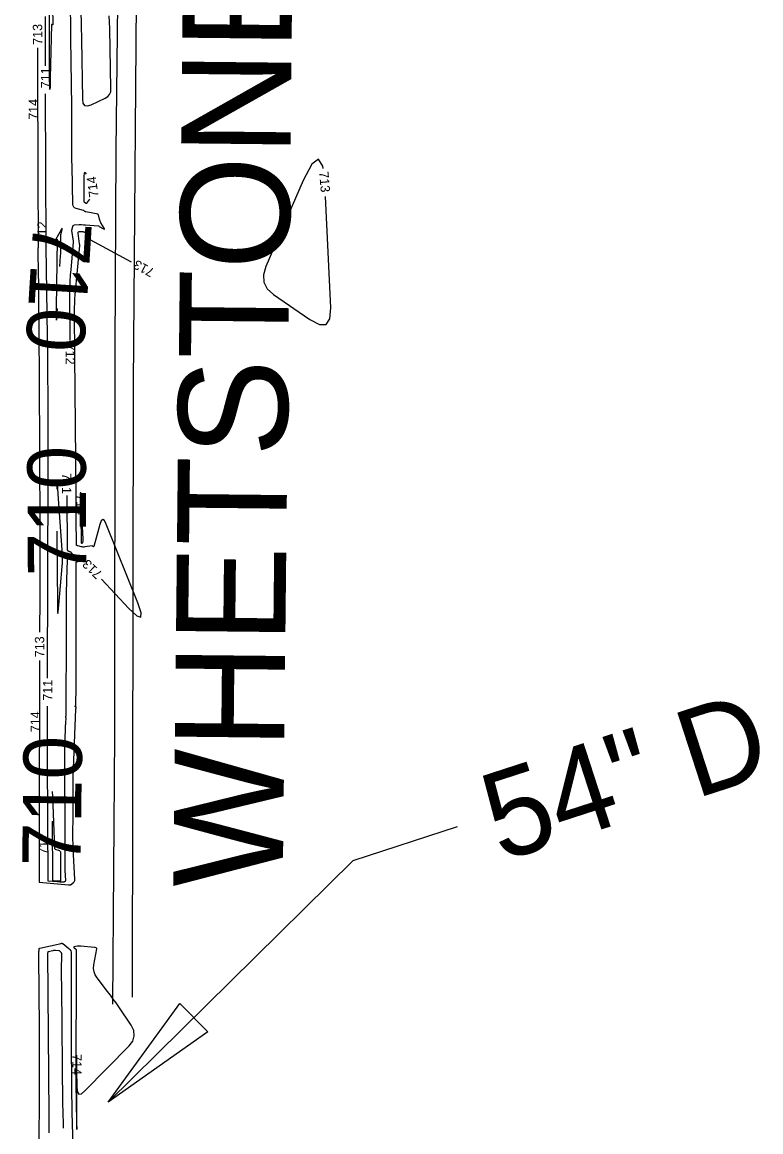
# Model space of a CAD drawing. Extents: x -468548933 to 3387700, y -306089263 to 1207014.
# Drawn here: x 1835224.3 to 1835540.3, y 536770.1 to 537244.7 of the extents above; entities that cross this region are included whole.
import ezdxf

# ---------------------------------------------------------------- set-up
doc = ezdxf.new("R2010")
doc.units = 0
for name, color, linetype in [('DT_X_Contour_Minor', 7, 'Continuous'), ('Level 19', 7, 'Continuous'), ('Level 40', 7, 'Continuous'), ('Level 56', 7, 'Continuous')]:
    doc.layers.add(name, color=color, linetype=linetype)

msp = doc.modelspace()

# ---------------------------------------------------------------- linework, layer by layer
at = {"layer": 'DT_X_Contour_Minor'}
for points in [[(1835245.53, 537208.54), (1835245.2, 537237.69), (1835245.13, 537243.93), (1835245.05, 537250.18), (1835244.96, 537256.42), (1835244.87, 537262.67), (1835244.29, 537300.93), (1835244.27, 537303.35), (1835244.26, 537305.76), (1835244.26, 537308.18), (1835244.29, 537310.6), (1835244.4, 537318.49), (1835244.43, 537320.18), (1835244.45, 537321.87), (1835244.47, 537323.56), (1835244.5, 537325.26), (1835244.63, 537334.22)], [(1835237.1, 537258.77), (1835237.41, 537243.69), (1835237.4, 537243.62), (1835237.38, 537243.59), (1835237.33, 537243.58), (1835237.27, 537243.61), (1835237.05, 537243.75), (1835237, 537243.76), (1835236.97, 537243.76), (1835236.95, 537243.74), (1835236.94, 537243.69), (1835236.35, 537220.78), (1835236.24, 537217.1), (1835236.16, 537215.87), (1835236.1, 537217.1), (1835236.07, 537220.78), (1835235.98, 537252.2)], [(1835249.44, 537249.82), (1835249.54, 537243.5), (1835249.64, 537237.19), (1835250.09, 537211.76), (1835250.35, 537210.1), (1835251.06, 537209.15), (1835252.22, 537208.93), (1835253.83, 537209.43), (1835259.82, 537212.23), (1835260.94, 537212.93), (1835261.73, 537213.84), (1835262.2, 537214.95), (1835262.33, 537216.26), (1835261.78, 537241.97), (1835261.6, 537247.47)], [(1835234.35, 537226.13), (1835234.34, 537229.07), (1835234.33, 537233.31), (1835234.29, 537247.16)], [(1835230.91, 537233.73), (1835230.92, 537229.63), (1835231.08, 537175.02), (1835231.09, 537171.97), (1835231.09, 537168.92), (1835231.1, 537165.87), (1835231.11, 537162.82), (1835231.15, 537148.61), (1835231.15, 537148.6), (1835231.15, 537148.59), (1835231.16, 537148.58), (1835231.16, 537148.57), (1835231.17, 537148.53), (1835231.18, 537148.53), (1835231.18, 537148.52), (1835231.18, 537148.51), (1835231.18, 537148.51), (1835231.11, 537148.17), (1835231.09, 537148.09), (1835231.08, 537148.02), (1835231.08, 537147.94), (1835231.08, 537147.87), (1835231.22, 537136.27), (1835231.25, 537133.79), (1835231.28, 537131.3), (1835231.3, 537128.82), (1835231.32, 537126.33), (1835231.58, 537093.92), (1835231.63, 537086.98), (1835231.67, 537080.03), (1835231.7, 537073.09), (1835231.72, 537066.14), (1835231.82, 537022.38), (1835231.83, 537016.41), (1835231.83, 537010.45), (1835231.83, 537004.49), (1835231.82, 536998.52), (1835231.78, 536983.74)], [(1835235.23, 536964.15), (1835235.46, 537051.06), (1835235.46, 537054.46), (1835235.47, 537057.86), (1835235.46, 537061.26), (1835235.46, 537064.66), (1835235.43, 537075.76), (1835235.43, 537078.14), (1835235.42, 537080.52), (1835235.4, 537082.9), (1835235.39, 537085.29), (1835235.32, 537093.64), (1835235.3, 537095.44), (1835235.29, 537097.23), (1835235.27, 537099.02), (1835235.25, 537100.81), (1835234.65, 537148.62), (1835234.65, 537148.64), (1835234.65, 537148.65), (1835234.65, 537148.66), (1835234.66, 537148.68), (1835234.67, 537148.73), (1835234.67, 537148.74), (1835234.67, 537148.75), (1835234.67, 537148.75), (1835234.66, 537148.76), (1835234.6, 537148.92), (1835234.58, 537148.96), (1835234.57, 537148.99), (1835234.57, 537149.03), (1835234.57, 537149.07), (1835234.38, 537214.13)], [(1835244.87, 537108.57), (1835244.79, 537128.99), (1835244.81, 537131.49), (1835244.89, 537133.99), (1835245.04, 537136.49), (1835245.24, 537138.98), (1835246.32, 537150.51), (1835246.33, 537150.56), (1835246.32, 537150.61), (1835246.32, 537150.67), (1835246.31, 537150.72), (1835246.26, 537150.89), (1835246.25, 537150.93), (1835246.24, 537150.96), (1835246.24, 537151), (1835246.23, 537151.04), (1835245.63, 537155.61), (1835245.62, 537155.63), (1835245.62, 537155.65), (1835245.62, 537155.67), (1835245.61, 537155.69), (1835245.6, 537155.76), (1835245.6, 537155.77), (1835245.6, 537155.79), (1835245.6, 537155.8), (1835245.61, 537155.81), (1835245.96, 537157.31), (1835246.07, 537157.59), (1835246.24, 537157.8), (1835246.48, 537157.93), (1835246.77, 537157.99), (1835248.66, 537158.12), (1835248.93, 537158.13), (1835249.2, 537158.14), (1835249.47, 537158.14), (1835249.73, 537158.14), (1835250.61, 537158.11), (1835250.8, 537158.1), (1835250.98, 537158.09), (1835251.17, 537158.08), (1835251.36, 537158.06), (1835256.97, 537157.61), (1835257.02, 537157.6), (1835257.07, 537157.58), (1835257.11, 537157.56), (1835257.15, 537157.52), (1835257.31, 537157.34), (1835257.31, 537157.33), (1835257.32, 537157.33), (1835257.32, 537157.32), (1835257.32, 537157.32), (1835257.31, 537157.3), (1835257.31, 537157.29), (1835257.31, 537157.29), (1835257.31, 537157.29), (1835257.32, 537157.29), (1835259.12, 537156.32), (1835259.43, 537156.19), (1835259.58, 537156.2), (1835259.58, 537156.35), (1835259.43, 537156.65), (1835258.04, 537158.89), (1835257.83, 537159.26), (1835257.66, 537159.64), (1835257.51, 537160.03), (1835257.39, 537160.43), (1835256.94, 537162.3), (1835256.93, 537162.33), (1835256.92, 537162.35), (1835256.91, 537162.38), (1835256.9, 537162.41), (1835256.87, 537162.51), (1835256.87, 537162.52), (1835256.86, 537162.54), (1835256.84, 537162.55), (1835256.82, 537162.55), (1835251.52, 537163.61), (1835251.41, 537163.64), (1835251.3, 537163.68), (1835251.2, 537163.73), (1835251.11, 537163.79), (1835250.81, 537164.03), (1835250.74, 537164.07), (1835250.67, 537164.11), (1835250.6, 537164.14), (1835250.52, 537164.17), (1835247.38, 537165.04), (1835246.78, 537165.29), (1835246.36, 537165.67), (1835246.1, 537166.18), (1835246, 537166.81), (1835245.67, 537183.09), (1835245.63, 537185.61), (1835245.6, 537188.14), (1835245.58, 537190.67), (1835245.57, 537193.2), (1835245.57, 537201.46), (1835245.57, 537203.23), (1835245.56, 537205), (1835245.55, 537206.77), (1835245.53, 537208.54)], [(1835353.04, 537182.16), (1835352.92, 537183.17), (1835351.07, 537186.07), (1835348.3, 537184.02), (1835344.61, 537177.03), (1835328.51, 537140.24), (1835327.51, 537136.72), (1835327.74, 537133.55), (1835329.21, 537130.73), (1835331.91, 537128.25)], [(1835250.76, 537179.05), (1835250.64, 537168.41), (1835250.66, 537168.24), (1835250.71, 537168.09), (1835250.8, 537167.95), (1835250.92, 537167.83), (1835251.49, 537167.4), (1835251.53, 537167.36), (1835251.58, 537167.34), (1835251.63, 537167.32), (1835251.69, 537167.3), (1835251.87, 537167.27), (1835251.9, 537167.27), (1835251.94, 537167.27), (1835251.97, 537167.29), (1835251.99, 537167.32), (1835253.24, 537168.96)], [(1835251.8, 537179.66), (1835251.46, 537180.24), (1835251.08, 537180.49), (1835250.85, 537180.1), (1835250.76, 537179.05)], [(1835331.91, 537128.25), (1835347.38, 537117.52), (1835351.49, 537115.36), (1835354.35, 537115.47), (1835355.96, 537117.84), (1835356.32, 537122.47), (1835354.1, 537170.22)], [(1835240.49, 537140.21), (1835240.77, 537144.78), (1835240.82, 537145.71), (1835240.86, 537146.64), (1835240.88, 537147.58), (1835240.88, 537148.51), (1835240.86, 537152.77), (1835240.86, 537152.82), (1835240.87, 537152.88), (1835240.87, 537152.93), (1835240.87, 537152.98), (1835240.9, 537153.23), (1835240.9, 537153.23), (1835240.9, 537153.23), (1835240.9, 537153.24), (1835240.9, 537153.24), (1835240.9, 537153.24), (1835240.9, 537153.24), (1835240.9, 537153.24), (1835240.9, 537153.24), (1835240.89, 537153.24), (1835240.89, 537153.31), (1835240.88, 537153.33), (1835240.88, 537153.34), (1835240.88, 537153.36), (1835240.88, 537153.37), (1835240.83, 537153.66), (1835240.83, 537153.72), (1835240.82, 537153.78), (1835240.83, 537153.84), (1835240.84, 537153.91), (1835241.37, 537156.1), (1835241.43, 537156.45), (1835241.41, 537156.59), (1835241.31, 537156.51), (1835241.11, 537156.2), (1835238.52, 537151.7), (1835238.48, 537151.61), (1835238.48, 537151.57), (1835238.52, 537151.57), (1835238.61, 537151.61)], [(1835258.24, 537006.5), (1835270, 536993.95), (1835273.33, 536990.8), (1835275.06, 536990.15), (1835275.21, 536992), (1835273.77, 536996.35), (1835260.33, 537030.03), (1835259.56, 537031.52), (1835258.84, 537031.99), (1835258.18, 537031.45), (1835257.57, 537029.89), (1835254.93, 537020.44), (1835254.89, 537020.36), (1835254.84, 537020.32), (1835254.79, 537020.33), (1835254.72, 537020.39), (1835254.47, 537020.64), (1835254.42, 537020.69), (1835254.35, 537020.72), (1835254.29, 537020.73), (1835254.22, 537020.73), (1835251.1, 537020.25), (1835250.73, 537020.21), (1835250.37, 537020.21), (1835250, 537020.25), (1835249.64, 537020.32), (1835248.08, 537020.71), (1835248.02, 537020.73), (1835247.96, 537020.75), (1835247.9, 537020.78), (1835247.84, 537020.81), (1835247.65, 537020.91), (1835247.62, 537020.94), (1835247.59, 537020.97), (1835247.58, 537021.01), (1835247.57, 537021.05), (1835247.49, 537032.53), (1835247.47, 537034.99), (1835247.45, 537037.45), (1835247.43, 537039.91), (1835247.41, 537042.37), (1835246.84, 537102.21), (1835246.82, 537104.79), (1835246.8, 537107.37), (1835246.79, 537109.95), (1835246.77, 537112.52), (1835246.74, 537120.95), (1835246.75, 537122.75), (1835246.81, 537124.56), (1835246.92, 537126.36), (1835247.06, 537128.16), (1835249.04, 537149.14), (1835249.04, 537149.22), (1835249.04, 537149.3), (1835249.03, 537149.38), (1835249.01, 537149.46), (1835248.94, 537149.71), (1835248.93, 537149.77), (1835248.92, 537149.82), (1835248.91, 537149.88), (1835248.9, 537149.94), (1835248.29, 537154.51), (1835248.3, 537154.86), (1835248.41, 537155.1), (1835248.65, 537155.23), (1835248.99, 537155.26), (1835250.31, 537155.16), (1835250.58, 537155.12), (1835250.83, 537155.03), (1835251.05, 537154.88), (1835251.25, 537154.69), (1835253.18, 537152.46), (1835253.22, 537152.4), (1835253.25, 537152.33), (1835253.26, 537152.25), (1835253.25, 537152.17), (1835253.19, 537151.9), (1835253.19, 537151.84), (1835253.2, 537151.8), (1835253.23, 537151.76), (1835253.27, 537151.73), (1835270.89, 537142.29)], [(1835238.61, 537151.61), (1835239.08, 537151.88), (1835239.2, 537151.94), (1835239.29, 537151.92), (1835239.35, 537151.85), (1835239.36, 537151.72), (1835238.92, 537122.47), (1835238.89, 537118.58), (1835238.96, 537117.27), (1835239.13, 537118.57), (1835239.38, 537122.24)], [(1835240.03, 536995.31), (1835241.45, 537011.91), (1835241.49, 537012.43), (1835241.52, 537012.94), (1835241.55, 537013.46), (1835241.56, 537013.98), (1835241.63, 537016.36), (1835241.63, 537016.38), (1835241.64, 537016.39), (1835241.65, 537016.41), (1835241.67, 537016.41), (1835241.73, 537016.44), (1835241.74, 537016.45), (1835241.74, 537016.45), (1835241.74, 537016.46), (1835241.73, 537016.47), (1835241.7, 537016.51), (1835241.69, 537016.52), (1835241.69, 537016.53), (1835241.68, 537016.54), (1835241.68, 537016.55), (1835241.63, 537016.75), (1835241.62, 537016.79), (1835241.61, 537016.84), (1835241.6, 537016.88), (1835241.6, 537016.93), (1835239.79, 537042.91), (1835239.46, 537047.09), (1835239.23, 537048.47), (1835239.11, 537047.07), (1835239.1, 537045.03)], [(1835243.37, 537042.2), (1835243.53, 537019.29), (1835243.55, 537019.12), (1835243.61, 537018.96), (1835243.72, 537018.84), (1835243.86, 537018.73), (1835244.5, 537018.37), (1835244.56, 537018.34), (1835244.63, 537018.31), (1835244.69, 537018.28), (1835244.76, 537018.26), (1835244.99, 537018.21), (1835245.03, 537018.19), (1835245.07, 537018.17), (1835245.09, 537018.13), (1835245.11, 537018.09), (1835245.17, 537017.91), (1835245.19, 537017.88), (1835245.2, 537017.84), (1835245.22, 537017.81), (1835245.25, 537017.77), (1835245.9, 537017), (1835246, 537016.85), (1835246.01, 537016.71), (1835245.94, 537016.59), (1835245.78, 537016.5), (1835244.23, 537015.82), (1835243.93, 537015.64), (1835243.72, 537015.41), (1835243.59, 537015.13), (1835243.54, 537014.8), (1835243.29, 537005.98), (1835243.24, 537004.09), (1835243.21, 537002.2), (1835243.19, 537000.31), (1835243.19, 536998.42), (1835243.19, 536991.11), (1835243.19, 536989.54), (1835243.19, 536987.97), (1835243.18, 536986.41), (1835243.18, 536984.84), (1835243.01, 536948.28), (1835243.01, 536948.23), (1835243, 536948.18), (1835242.99, 536948.13), (1835242.98, 536948.08), (1835242.94, 536947.92), (1835242.93, 536947.89), (1835242.93, 536947.86), (1835242.92, 536947.82), (1835242.92, 536947.79), (1835242.91, 536947.21), (1835242.91, 536947.2), (1835242.91, 536947.19), (1835242.92, 536947.18), (1835242.94, 536947.18), (1835242.99, 536947.18), (1835243, 536947.18), (1835243.01, 536947.17), (1835243.01, 536947.17), (1835243.01, 536947.16), (1835242.84, 536944.83), (1835242.81, 536944.33), (1835242.78, 536943.83), (1835242.76, 536943.33), (1835242.73, 536942.84), (1835242.54, 536937.89), (1835242.51, 536936.83), (1835242.48, 536935.78), (1835242.47, 536934.72), (1835242.47, 536933.66), (1835242.64, 536889.68), (1835242.64, 536888.91), (1835242.64, 536888.13), (1835242.64, 536887.35), (1835242.63, 536886.57), (1835242.61, 536884.03), (1835242.61, 536883.49), (1835242.61, 536882.95), (1835242.63, 536882.4), (1835242.65, 536881.86), (1835242.88, 536877.62), (1835242.87, 536877.49), (1835242.84, 536877.38), (1835242.78, 536877.28), (1835242.69, 536877.19), (1835242.35, 536876.93), (1835242.28, 536876.88), (1835242.2, 536876.84), (1835242.11, 536876.83), (1835242.02, 536876.82), (1835240.54, 536876.91), (1835240.22, 536876.93), (1835239.9, 536876.95), (1835239.58, 536876.97), (1835239.26, 536877), (1835235.44, 536877.35), (1835235.44, 536877.35), (1835235.43, 536877.35), (1835235.43, 536877.36), (1835235.43, 536877.36)], [(1835249.6, 537021.97), (1835249.61, 537021.97), (1835249.61, 537021.96), (1835249.62, 537021.96), (1835249.62, 537021.96), (1835249.63, 537021.96), (1835249.75, 537021.93), (1835249.77, 537021.92), (1835249.8, 537021.92), (1835249.82, 537021.92), (1835249.85, 537021.92), (1835250.1, 537021.96), (1835250.15, 537021.98), (1835250.19, 537022), (1835250.21, 537022.04), (1835250.23, 537022.08), (1835250.42, 537022.85), (1835250.46, 537023.01), (1835250.48, 537023.17), (1835250.49, 537023.34), (1835250.48, 537023.51), (1835250.01, 537031.77), (1835249.92, 537033.31), (1835249.84, 537034.85), (1835249.76, 537036.39), (1835249.69, 537037.94), (1835249.47, 537042.97), (1835249.43, 537043.73)], [(1835249.49, 537032.38), (1835249.58, 537023.58), (1835249.58, 537023.4), (1835249.58, 537023.21), (1835249.58, 537023.03), (1835249.58, 537022.84), (1835249.59, 537021.98), (1835249.59, 537021.98), (1835249.59, 537021.98), (1835249.59, 537021.98), (1835249.6, 537021.97)], [(1835239.18, 537027.03), (1835239.38, 536995.34), (1835239.44, 536992.66), (1835239.56, 536991.76), (1835239.76, 536992.65), (1835240.03, 536995.31)], [(1835231.75, 536971.74), (1835231.74, 536970.7), (1835231.73, 536966.52), (1835231.72, 536962.35), (1835231.54, 536906.14), (1835231.53, 536902.78), (1835231.53, 536899.42), (1835231.54, 536896.05), (1835231.55, 536892.69), (1835231.63, 536877.04), (1835231.63, 536877.02), (1835231.63, 536877), (1835231.63, 536876.98), (1835231.62, 536876.96), (1835231.62, 536876.89), (1835231.62, 536876.88), (1835231.62, 536876.87), (1835231.63, 536876.86), (1835231.64, 536876.86), (1835244.16, 536875.72), (1835244.24, 536875.72), (1835244.33, 536875.71), (1835244.41, 536875.7), (1835244.5, 536875.7), (1835244.78, 536875.68), (1835244.84, 536875.68), (1835244.89, 536875.7), (1835244.94, 536875.72), (1835244.99, 536875.75), (1835246.3, 536876.78), (1835246.55, 536877.01), (1835246.72, 536877.29), (1835246.81, 536877.59), (1835246.83, 536877.93), (1835246.25, 536888.74), (1835246.15, 536890.96), (1835246.08, 536893.17), (1835246.05, 536895.39), (1835246.05, 536897.61), (1835246.12, 536904.85), (1835246.13, 536906.4), (1835246.14, 536907.96), (1835246.14, 536909.51), (1835246.14, 536911.06), (1835246.12, 536916.86), (1835246.12, 536918.1), (1835246.13, 536919.34), (1835246.16, 536920.58), (1835246.2, 536921.83), (1835247.34, 536950.87), (1835247.35, 536950.98), (1835247.35, 536951.09), (1835247.36, 536951.21), (1835247.37, 536951.32), (1835247.4, 536951.74), (1835247.39, 536951.78), (1835247.38, 536951.81), (1835247.34, 536951.83), (1835247.3, 536951.84), (1835247.1, 536951.84), (1835247.08, 536951.84), (1835247.07, 536951.85), (1835247.06, 536951.86), (1835247.06, 536951.88), (1835247.06, 536951.95), (1835247.06, 536951.97), (1835247.06, 536951.99), (1835247.07, 536952), (1835247.07, 536952.02), (1835247.27, 536952.71), (1835247.3, 536952.87), (1835247.33, 536953.02), (1835247.35, 536953.17), (1835247.35, 536953.33), (1835247.38, 536959.64), (1835247.39, 536961), (1835247.39, 536962.35), (1835247.39, 536963.7), (1835247.39, 536965.06), (1835247.37, 537011.6), (1835247.37, 537011.85), (1835247.37, 537012.1), (1835247.38, 537012.35), (1835247.38, 537012.6), (1835247.41, 537013.61), (1835247.42, 537013.69), (1835247.45, 537013.75), (1835247.5, 537013.8), (1835247.56, 537013.84), (1835247.8, 537013.94), (1835247.85, 537013.96), (1835247.91, 537013.98), (1835247.96, 537014), (1835248.01, 537014.02), (1835248.36, 537014.11), (1835248.44, 537014.13), (1835248.51, 537014.16), (1835248.59, 537014.18), (1835248.66, 537014.21), (1835249.79, 537014.64)], [(1835235.43, 536877.36), (1835235.43, 536877.39), (1835235.44, 536877.39), (1835235.44, 536877.4), (1835235.44, 536877.4), (1835235.44, 536877.41), (1835235.18, 536929.66), (1835235.17, 536933.08), (1835235.16, 536936.51), (1835235.16, 536939.93), (1835235.17, 536943.36), (1835235.2, 536952.15)], [(1835237.34, 536877.6), (1835237.34, 536877.6), (1835237.34, 536877.59), (1835237.34, 536877.59), (1835237.34, 536877.59), (1835237.34, 536877.59), (1835237.58, 536877.57), (1835237.63, 536877.57), (1835237.69, 536877.56), (1835237.74, 536877.56), (1835237.79, 536877.56), (1835240.84, 536877.38), (1835240.85, 536877.38), (1835240.86, 536877.38), (1835240.87, 536877.39), (1835240.87, 536877.39), (1835240.9, 536877.41), (1835240.9, 536877.42), (1835240.91, 536877.42), (1835240.91, 536877.43), (1835240.91, 536877.43), (1835240.89, 536877.72), (1835240.89, 536877.78), (1835240.89, 536877.83), (1835240.89, 536877.89), (1835240.89, 536877.95), (1835240.89, 536878.14), (1835240.89, 536878.18), (1835240.89, 536878.22), (1835240.89, 536878.26), (1835240.89, 536878.3), (1835240.85, 536889.39), (1835240.8, 536889.75), (1835240.65, 536890.04), (1835240.41, 536890.25), (1835240.07, 536890.39), (1835238.81, 536890.73), (1835238.58, 536890.83), (1835238.4, 536890.98), (1835238.3, 536891.18), (1835238.25, 536891.44), (1835237.46, 536913.54), (1835237.37, 536915.59)], [(1835237.21, 536902.98), (1835237.34, 536877.6), (1835237.34, 536877.6), (1835237.34, 536877.6), (1835237.34, 536877.6), (1835237.34, 536877.6)], [(1835231.64, 536738.44), (1835231.7, 536811.98), (1835231.7, 536816.06), (1835231.69, 536820.13), (1835231.67, 536824.21), (1835231.65, 536828.29), (1835231.51, 536846.93), (1835231.51, 536847.12), (1835231.52, 536847.31), (1835231.53, 536847.5), (1835231.55, 536847.68), (1835231.63, 536848.3), (1835231.66, 536848.42), (1835231.71, 536848.51), (1835231.8, 536848.58), (1835231.91, 536848.62), (1835240.95, 536850.67), (1835241.02, 536850.69), (1835241.09, 536850.69), (1835241.17, 536850.7), (1835241.24, 536850.69), (1835241.49, 536850.67), (1835241.54, 536850.66), (1835241.59, 536850.65), (1835241.63, 536850.63), (1835241.67, 536850.6), (1835244.26, 536848.5), (1835244.74, 536848.02), (1835245.09, 536847.47), (1835245.29, 536846.86), (1835245.36, 536846.18), (1835245.31, 536809.73), (1835245.31, 536806.61), (1835245.32, 536803.5), (1835245.34, 536800.39), (1835245.37, 536797.27), (1835245.48, 536787.1), (1835245.5, 536784.92), (1835245.54, 536782.74), (1835245.58, 536780.56), (1835245.63, 536778.38), (1835245.97, 536763.96)], [(1835241.98, 536771.64), (1835241.98, 536772.24), (1835241.95, 536773.58), (1835241.84, 536777.95), (1835241.82, 536778.88), (1835241.81, 536779.82), (1835241.79, 536780.76), (1835241.78, 536781.69), (1835241.25, 536831.98), (1835241.23, 536833.68), (1835241.22, 536835.37), (1835241.22, 536837.07), (1835241.22, 536838.77), (1835241.23, 536846.32), (1835241.21, 536846.5), (1835241.16, 536846.66), (1835241.07, 536846.8), (1835240.94, 536846.93), (1835240.46, 536847.31), (1835240.36, 536847.38), (1835240.25, 536847.44), (1835240.13, 536847.48), (1835240, 536847.5), (1835238.58, 536847.61), (1835238.28, 536847.63), (1835237.98, 536847.62), (1835237.68, 536847.58), (1835237.38, 536847.53), (1835235.38, 536847.07), (1835235.33, 536847.06), (1835235.3, 536847.03), (1835235.28, 536846.99), (1835235.26, 536846.94), (1835235.24, 536846.77), (1835235.24, 536846.73), (1835235.24, 536846.69), (1835235.24, 536846.65), (1835235.23, 536846.62), (1835235.74, 536777.14), (1835235.77, 536773.41), (1835235.78, 536769.67)], [(1835247.77, 536792.79), (1835247.77, 536788.95), (1835247.98, 536787.03), (1835248.62, 536786.16), (1835249.69, 536786.33), (1835251.18, 536787.55), (1835270.07, 536806.79), (1835271.64, 536808.9), (1835272.3, 536811.09), (1835272.05, 536813.36), (1835270.89, 536815.71), (1835265.62, 536823.55), (1835264.48, 536825.22), (1835263.31, 536826.87), (1835262.11, 536828.5), (1835260.89, 536830.11), (1835256.39, 536835.94), (1835255.59, 536837.21), (1835255.09, 536838.56), (1835254.9, 536839.98), (1835255.01, 536841.48), (1835256.2, 536848.37), (1835256.2, 536848.49), (1835256.17, 536848.59), (1835256.1, 536848.67), (1835255.99, 536848.72), (1835255.58, 536848.86), (1835255.49, 536848.89), (1835255.4, 536848.91), (1835255.31, 536848.93), (1835255.22, 536848.94), (1835249.46, 536849.51), (1835249.07, 536849.54), (1835248.69, 536849.53), (1835248.31, 536849.5), (1835247.93, 536849.44), (1835246.64, 536849.18), (1835246.46, 536849.12), (1835246.38, 536849.03), (1835246.41, 536848.92), (1835246.54, 536848.78), (1835247.16, 536848.28), (1835247.28, 536848.16), (1835247.36, 536848.03), (1835247.41, 536847.88), (1835247.43, 536847.72)], [(1835247.43, 536847.72), (1835247.35, 536788.57), (1835247.35, 536788.07), (1835247.35, 536787.56), (1835247.35, 536787.06), (1835247.36, 536786.55), (1835247.38, 536784.9), (1835247.38, 536784.55), (1835247.39, 536784.19), (1835247.39, 536783.84), (1835247.4, 536783.49), (1835247.64, 536773.29), (1835247.69, 536771.65), (1835247.72, 536771.1), (1835247.74, 536771.65), (1835247.75, 536773.29), (1835247.76, 536800.34), (1835247.77, 536802.86)]]:
    msp.add_lwpolyline(points, dxfattribs=at)
at = {"layer": 'Level 40'}
for p, q in [((1835261.05, 536782.68), (1835291.73, 536825)), ((1835291.73, 536825), (1835303.78, 536812.79)), ((1835303.78, 536812.79), (1835261.05, 536782.68))]:
    msp.add_line(p, q, dxfattribs=at)
msp.add_lwpolyline([(1835261.05, 536782.67), (1835365.89, 536886.16), (1835410.53, 536900.65)], dxfattribs=at)
at = {"layer": 'Level 56'}
for points in [[(1835272.54, 537989.9), (1835270.63, 537829.71), (1835268.58, 537639.91), (1835267.46, 537489.92), (1835266.63, 537389.92), (1835264.41, 537189.93), (1835263.9, 537104.93), (1835263.77, 536939.93), (1835262.99, 536824.67)], [(1835271.56, 536827.69), (1835271.95, 537089.9), (1835273.57, 537289.9), (1835275.29, 537464.69), (1835276.71, 537656.89), (1835279.46, 537914.68), (1835280.54, 537989.88)]]:
    msp.add_lwpolyline(points, dxfattribs=at)

# ---------------------------------------------------------------- texts
at = {"layer": 'Level 19'}
for s, height, rotation, p in [('713', 4, 90.0827, (1835232.9, 537235.05)), ('711', 4, 90.1628, (1835236.38, 537216.48)), ('714', 4, 89.9462, (1835231.15, 537202.99)), ('714', 4, 97.6991, (1835257.03, 537170.11)), ('713', 4, 275.0531, (1835351.35, 537180.69)), ('710', 25, 266.47, (1835229.21, 537160.29)), ('712', 4, 90.1621, (1835234.85, 537150.59)), ('713', 4, 151.8251, (1835281.25, 537139.01)), ('712', 4, 270.2684, (1835242.88, 537107.21)), ('710', 25, 90.2794, (1835251.77, 537007.74)), ('711', 4, 270.3958, (1835241.31, 537051.84)), ('714', 4, 270.319, (1835247.41, 537042.84)), ('713', 4, 136.0838, (1835258.89, 537009.08)), ('713', 4, 89.8465, (1835233.75, 536973.06)), ('711', 4, 89.8316, (1835237.2, 536954.49)), ('714', 4, 89.8185, (1835231.9, 536941.01)), ('710', 25, 89.2801, (1835249.31, 536883.47)), ('712', 4, 90.2805, (1835235.48, 536888.61)), ('714', 4, 270.0012, (1835245.77, 536803.27))]:
    msp.add_text(s, height=height, rotation=rotation, dxfattribs=at).set_placement(p)
at = {"layer": 'Level 40'}
for s, height, rotation, p in [('WHETSTONE RD.', 46.8, 89.3978, (1835335.8, 536874.43)), ('54" D', 37.5, 17.9864, (1835429.05, 536885.4))]:
    msp.add_text(s, height=height, rotation=rotation, dxfattribs=at).set_placement(p)

doc.saveas('drawing.dxf')
